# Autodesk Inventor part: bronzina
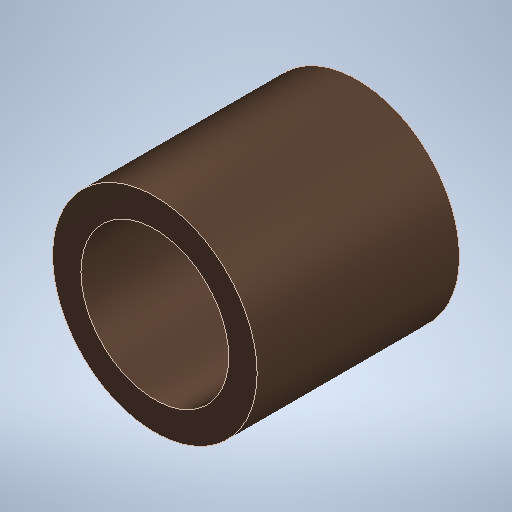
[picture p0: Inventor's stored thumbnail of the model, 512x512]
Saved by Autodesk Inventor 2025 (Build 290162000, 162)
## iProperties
Created: 2025-10
Part Number: bronzina
Material: Generico
Document SubType Name: Modeling
Designer: 18619647
Density: 1 g/cm^3
Appearance: Bronzo - Satinato
Author: 18619647
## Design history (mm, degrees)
sketch "Schizzo1"
  geometry: C1 r 9 at (0, 0); C2 r 6.5 at (0, 0); 1 further point
  constraints: 2 centre point, 2 coincident
  dimensions: "d0" = 18 diameter of C1; "d1" = 13 diameter of C2
extrude "Estrusione1" new body sketch "Schizzo1" distance "d2" = 17.8; taper "d3" = 0 deg
node "Solido1"
